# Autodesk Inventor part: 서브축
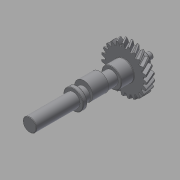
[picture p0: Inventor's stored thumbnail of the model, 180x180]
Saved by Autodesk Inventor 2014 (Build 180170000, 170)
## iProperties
Created: 2016-12
Part Number: 서브축
Material: 강철, 탄소
Document SubType Name: Modeling
Designer: mduedu
Categories: <?xml version="1.0" encoding="UTF-16"?> <MemberInstance><Categories><FamilyTemplate><FamilyTemplateParameter ValueType="xs:double" Id="1" ObjectReferenceKey="da
Density: 7.87 g/cm^3
Appearance: Default
Mass: 483.642 g
Surface Area: 167.142 cm^2
Volume: 61.4539 cm^3
CustomPartVersion: 1
Author: mduedu
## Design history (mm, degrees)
sketch "Sketch1"
  geometry: C1 r 28.558 at (0, 0)
  constraints: 1 centre point
  dimensions: "d0" = 57.11622 diameter of C1 (= da_da)
extrude "Extrusion1" new body sketch "Sketch1" distance "d1" = 10 (= da_b); taper "d2" = 0 deg
workplane "Work Plane2"
sketch "Sketch2"
  geometry: C1 r 28.558 at (0, 0) reference; C2 r 26.558 at (0, 0)
  constraints: 1 centre point, 1 coincident
  dimensions: "d3" = 53.11622 diameter of C2 (= da_dw)
feature "피치 지름" sketch "Sketch2" dims "d4" = 10, "d5" = 0
workplane "Work Plane8"
workplane "Work Plane9"
feature "스퍼 기어" dims "da_b" = 10, "da_d" = 53.11622, "da_aw" = 43.87862, "da_da" = 57.11622, "da_df" = 48.11622, "da_dw" = 53.11622, angle "da_beta" = 30 deg, "da_lefttooth" = 10, "da_righttooth" = 0
sketch "스케치3"
  geometry: C1 r 12.5 at (0, 0); 1 further point
  constraints: 1 centre point, 1 coincident
  dimensions: "d49" = 25 diameter of C1
extrude "돌출2" join sketch "스케치3" distance "d50" = 16; taper "d51" = 0 deg
sketch "스케치4"
  geometry: C1 r 8.5 at (0, 0); 1 further point
  constraints: 1 centre point, 1 coincident
  dimensions: "d52" = 17 diameter of C1
extrude "돌출3" join sketch "스케치4" distance "d53" = 103; taper "d54" = 0 deg
sketch "스케치5"
  geometry: C1 r 7.5 at (0, 0); 1 further point
  constraints: 1 centre point, 1 coincident
  dimensions: "d55" = 15 diameter of C1
extrude "돌출4" join sketch "스케치5" distance "d56" = 16; taper "d57" = 0 deg
sketch "스케치6"
  geometry: C1 r 4 at (0, 0); 1 further point
  constraints: 1 centre point, 1 coincident
  dimensions: "d58" = 8 diameter of C1
extrude "돌출5" join sketch "스케치6" distance "d59" = 7; taper "d60" = 0 deg
chamfer "모따기1" distance "d61" = 0.5; stored, may be unused: second distance "d62" = 2, angle "d63" = 45 deg
fillet "모깎기1" dims "d64" = 0.5
node "작업 평면11"
sketch "스케치7"
  geometry: C1 r 11.5 at (0, 3); C2 r 8.5 at (0, 0) reference; 1 further point
  constraints: 1 centre point, 1 tangent, 1 vertical alignment
  dimensions: "d66" = 3 distance of point (0, 0) C1.centre; "d67" = 23 diameter of C1 (derived)
extrude "돌출6" join sketch "스케치7" stored distance "d68" = 20; taper "d69" = 0 deg
node "작업 평면12"
sketch "스케치8"
  geometry: C1 r 12.5 at (0, 0) reference; 1 further point
extrude "돌출7" join sketch "스케치8" distance "d71" = 5; taper "d72" = 0 deg
chamfer "모따기2" distance "d73" = 0.5; stored, may be unused: second distance "d74" = 2, angle "d75" = 45 deg
body "Solid1"
body "Srf1"
other parameters: "d16" = 43.87862 (= da_aw), "d17" = 0, "d34" = 1.36591 (computed from da_z), "d39" = 0, "d41" = 0, "d43" = 43.87862 (= da_aw), "d46" = 43.87862 (= da_aw), "d47" = 0, "d48" = 0, "d65" = 25, "d70" = 48
